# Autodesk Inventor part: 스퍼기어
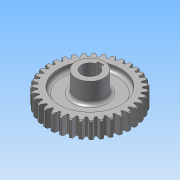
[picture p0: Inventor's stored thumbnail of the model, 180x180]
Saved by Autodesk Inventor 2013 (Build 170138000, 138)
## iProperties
Created: 2013-08
Part Number: 스퍼기어
Material: 강
Document SubType Name: Modeling
Designer: 한국산업디자인학원
Categories: <?xml version="1.0" encoding="UTF-16"?> <MemberInstance><Categories><FamilyTemplate><FamilyTemplateParameter ValueType="xs:double" Id="1" ObjectReferenceKey="da
Density: 1 g/cm^3
CustomPartVersion: 1
Author: 한국산업디자인학원
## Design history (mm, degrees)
sketch "Sketch1"
  geometry: C1 r 37 at (0, 0)
  constraints: 1 centre point
  dimensions: "d0" = 74 diameter of C1 (= da_da)
extrude "Extrusion1" new body sketch "Sketch1" distance "d1" = 15 (= da_b); taper "d2" = 0 deg
sketch "스케치3"
  geometry: C1 r 37 at (0, 0) reference; C2 r 12.5 at (0, 0)
  constraints: 1 centre point, 1 coincident
  dimensions: "d49" = 25 diameter of C2
extrude "돌출2" join sketch "스케치3" distance "d51" = 13; taper "d52" = 0 deg
sketch "스케치4"
  geometry: C1 r 37 at (0, 0) reference; C2 r 12.5 at (0, 0)
  constraints: 1 centre point, 1 coincident
  dimensions: "d53" = 25 diameter of C2
extrude "돌출3" join sketch "스케치4" distance "d55" = 3; taper "d56" = 0 deg
sketch "스케치5"
  geometry: L1 (-2.5, 7.071)-(-2.5, 9.8); L2 (-2.5, 9.8)-(2.5, 9.8); L3 (2.5, 9.8)-(2.5, 7.071); C1 r 12.5 at (0, 0) reference; A1 r 7.5 centre (0, 0) between (-2.5, 7.071) and (2.5, 7.071)
  constraints: 6 end point, 2 perpendicular, 2 point on circle, 1 centre point, 1 coincident, 1 parallel, 1 vertical
  dimensions: "d57" = 15 diameter of A1; "d59" = 5 distance of L1.end L2.end; "d60" = 17.3 dimension on A1 L2
extrude "돌출4" cut sketch "스케치5" stored distance "d61" = 0; taper "d62" = 0 deg
sketch "스케치6"
  geometry: C1 r 12.5 at (0, 0) reference; C2 r 37 at (0, 0) reference; C3 r 27.5 at (0, 0)
  constraints: 1 centre point, 1 coincident
  dimensions: "d63" = 55 diameter of C3
extrude "돌출5" cut sketch "스케치6" distance "d65" = 5; taper "d66" = 0 deg
node "작업 평면11"
chamfer "모따기1" distance "d67" = 1; stored, may be unused: second distance "d68" = 2, angle "d69" = 45 deg
fillet "모깎기1" dims "d70" = 3
fillet "모깎기2" dims "d71" = 3
workplane "Work Plane2"
feature "피치 지름" dims "d4" = 10, "d5" = 0
workplane "Work Plane8"
workplane "Work Plane9"
feature "스퍼 기어" dims "da_b" = 15, "da_d" = 70, "da_aw" = 70, "da_da" = 74, "da_df" = 65, "da_dw" = 70, angle "da_beta" = 0 deg, "da_lefttooth" = 0, "da_righttooth" = 0
body "Solid1"
mirror "대칭1"
sketch "Sketch2"
  geometry: C1 r 37 at (0, 0) reference; C2 r 35 at (0, 0)
  constraints: 1 centre point, 1 coincident
  dimensions: "d3" = 70 diameter of C2 (= da_dw)
body "Srf1"
other parameters: "d17" = 0, "d34" = 0.8976 (computed from da_z), "d39" = 0, "d41" = 0, "d47" = 0, "d48" = 0
